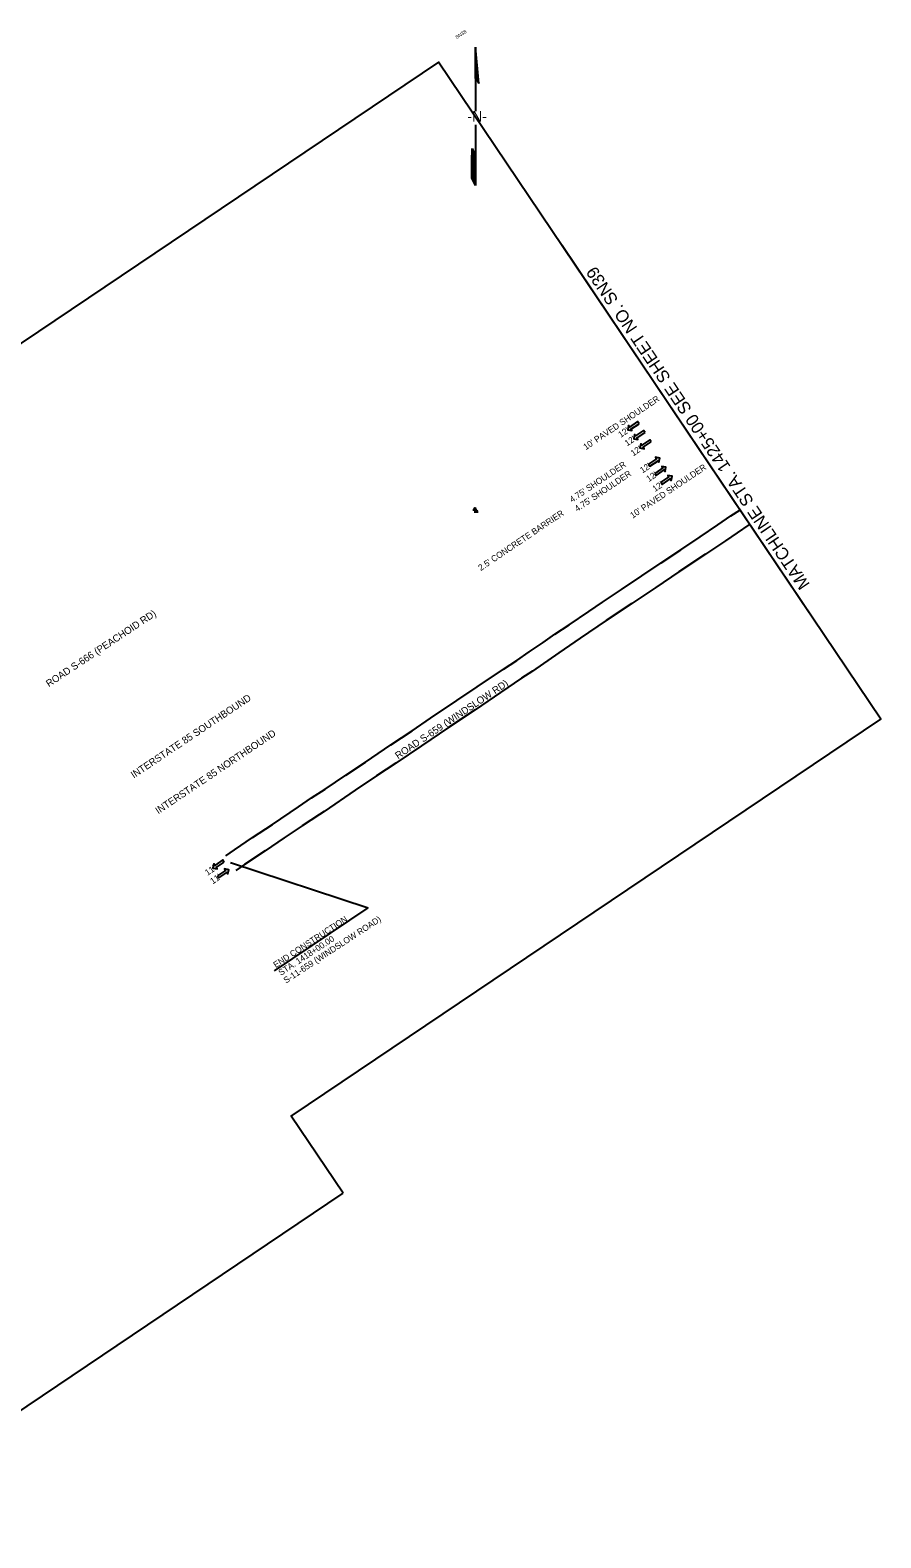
# Model space of a CAD drawing. Extents: x 1789464 to 1791208, y 1183240 to 1184943.
# Drawn here: x 1790247 to 1791208, y 1183240 to 1184943 of the extents above; entities that cross this region are included whole.
import ezdxf

# ---------------------------------------------------------------- set-up
doc = ezdxf.new("R2010")
doc.units = 0
for name, color, linetype in [('RD_EX_Road', 7, 'Continuous'), ('RD_PD_Final_LnLine', 7, 'Continuous'), ('RD_PD_Final_TX', 7, 'Continuous'), ('RD_SHT_MatchLine', 7, 'Continuous'), ('RD_SHT_ShtClip', 7, 'Continuous'), ('RD_SHT_TX', 7, 'Continuous'), ('RD_Sketch1', 7, 'Continuous'), ('RD_TX_RoadID', 7, 'Continuous'), ('SN_P_Signs', 7, 'Continuous')]:
    doc.layers.add(name, color=color, linetype=linetype)

# ---------------------------------------------------------------- blocks, each defined once
blk = doc.blocks.new('NA5')
at = {"layer": 'RD_Sketch1'}
for p, q in [((47.5, 65.9), (26.8, 37.4)), ((26.8, 30.6), (47.5, 65.9)), ((27.2, 37.5), (14.5, 19.8)), ((28.1, 38.3), (26.8, 30.6)), ((14.5, 19.8), (5.5, 7.2)), ((-3.5, -5.3), (-18.5, -26.3)), ((-18.5, -26.3), (-43.3, -60.9)), ((-30.6, -36.2), (-22.3, -24.7)), ((-22.3, -24.7), (-24, -34)), ((-41.6, -51.6), (-30.6, -36.2)), ((-43.3, -60.9), (-41.6, -51.6))]:
    blk.add_line(p, q, dxfattribs=at)
for points in [[(27.1, 37.6), (39.2, 54.5)], [(27.4, 37.8), (47.4, 65.8)], [(27.6, 37.9), (46.9, 64.9)], [(27.6, 35.5), (39, 51.5)], [(27.7, 36.2), (40.6, 54.2)], [(27.7, 36), (40.1, 53.3)], [(27.7, 35.8), (39.6, 52.4)], [(27.8, 38.1), (46.4, 64)], [(27.8, 36.8), (42.2, 56.8)], [(27.8, 36.6), (41.7, 56)], [(27.8, 36.4), (41.1, 55.1)], [(27.9, 37.4), (43.8, 59.5)], [(27.9, 37.2), (43.2, 58.6)], [(27.9, 37), (42.7, 57.7)], [(28, 38.1), (45.3, 62.2)], [(28, 37.9), (44.8, 61.3)], [(28, 37.7), (44.3, 60.4)], [(28.1, 38.3), (45.8, 63.1)], [(26.9, 37.5), (29.9, 41.7)], [(27, 32), (30.1, 36.3)], [(27, 31.8), (29.6, 35.4)], [(27, 31.5), (29.1, 34.5)], [(27.1, 32.6), (31.7, 39)], [(27.1, 32.4), (31.2, 38.1)], [(27.1, 32.2), (30.6, 37.2)], [(27.2, 33.2), (33.3, 41.6)], [(27.2, 33), (32.7, 40.7)], [(27.2, 32.8), (32.2, 39.9)], [(27.3, 33.9), (34.8, 44.3)], [(27.3, 33.7), (34.3, 43.4)], [(27.3, 33.4), (33.8, 42.5)], [(27.4, 34.5), (36.4, 47)], [(27.4, 34.3), (35.9, 46.1)], [(27.4, 34.1), (35.4, 45.2)], [(27.5, 34.9), (37.5, 48.8)], [(27.5, 34.7), (36.9, 47.9)], [(27.6, 35.3), (38.5, 50.6)], [(27.6, 35.1), (38, 49.7)], [(26.8, 30.7), (27, 30.9)], [(26.9, 31.3), (28.5, 33.6)], [(26.9, 31.1), (28, 32.7)], [(26.9, 30.9), (27.5, 31.8)], [(-43.3, -60.8), (-24, -33.9)], [(-43.2, -60.1), (-23.9, -33.2)], [(-43.2, -60.3), (-23.9, -33.4)], [(-43.2, -60.5), (-24, -33.6)], [(-43.1, -59.7), (-23.8, -32.8)], [(-43.1, -59.9), (-23.9, -33)], [(-43, -59), (-23.7, -32.1)], [(-43, -59.2), (-23.7, -32.3)], [(-43, -59.4), (-23.8, -32.5)], [(-42.9, -58.6), (-23.6, -31.7)], [(-42.9, -58.8), (-23.7, -31.9)], [(-42.8, -58.1), (-23.5, -31.2)], [(-42.8, -58.3), (-23.6, -31.4)], [(-42.7, -57.5), (-23.4, -30.6)], [(-42.7, -57.7), (-23.5, -30.8)], [(-42.7, -57.9), (-23.5, -31)], [(-42.6, -57), (-23.3, -30.1)], [(-42.6, -57.2), (-23.4, -30.4)], [(-42.5, -56.4), (-23.2, -29.5)], [(-42.5, -56.6), (-23.2, -29.7)], [(-42.5, -56.8), (-23.3, -29.9)], [(-42.4, -55.9), (-23.1, -29)], [(-42.4, -56.1), (-23.2, -29.3)], [(-42.3, -55.3), (-23, -28.4)], [(-42.3, -55.5), (-23, -28.6)], [(-42.3, -55.7), (-23.1, -28.8)], [(-42.2, -54.8), (-22.9, -27.9)], [(-42.2, -55), (-23, -28.2)], [(-42.1, -54.4), (-22.8, -27.5)], [(-42.1, -54.6), (-22.9, -27.7)], [(-42, -53.7), (-22.7, -26.8)], [(-42, -53.9), (-22.7, -27.1)], [(-42, -54.2), (-22.8, -27.3)], [(-41.9, -53.3), (-22.6, -26.4)], [(-41.9, -53.5), (-22.7, -26.6)], [(-41.8, -52.6), (-22.5, -25.7)], [(-41.8, -52.8), (-22.5, -26)], [(-41.8, -53.1), (-22.6, -26.2)], [(-41.7, -52.2), (-22.4, -25.3)], [(-41.7, -52.4), (-22.5, -25.5)], [(-41.6, -51.7), (-22.3, -24.9)], [(-41.6, -52), (-22.4, -25.1)]]:
    blk.add_lwpolyline(points, dxfattribs=at)
blk.add_text('-N-', height=11.81, rotation=324.3865, dxfattribs=at).set_placement((-8.8, 3))
blk = doc.blocks.new('SARRW2')
at = {"layer": 'RD_PD_Final_LnLine'}
blk.add_lwpolyline([(-12, 1.2), (-12, -1.2), (-2.8, -1.2), (-2.8, -2.8), (0, 0), (-2.8, 2.8), (-2.8, 1.2)], close=True, dxfattribs=at)

msp = doc.modelspace()

# ---------------------------------------------------------------- linework, layer by layer
at = {"layer": 'RD_EX_Road'}
for points in [[(1790468.4, 1184010.8), (1790478.3, 1184017.5), (1790498.6, 1184031.4), (1790521.1, 1184046.2), (1790550.5, 1184066.1), (1790565.3, 1184076), (1790580.8, 1184086), (1790603.9, 1184101.6), (1790626.2, 1184116.6), (1790654.7, 1184135.9), (1790678.9, 1184152), (1790699.8, 1184166.2), (1790729.5, 1184186.3), (1790752.4, 1184201.5), (1790782.3, 1184221.4), (1790797, 1184231.5), (1790811.2, 1184241.1), (1790826.9, 1184251.6), (1790840.3, 1184260.9), (1790856.3, 1184271.5), (1790878.6, 1184286.5), (1790894, 1184297.1), (1790915.3, 1184311.5), (1790938.3, 1184326.9), (1790960.4, 1184341.7), (1790982.5, 1184356.4), (1791004.3, 1184371.2), (1791024.1, 1184384.5), (1791039.1, 1184394.7), (1791049, 1184401.3), (1791049.3, 1184401.5)], [(1791060.3, 1184385.1), (1791059.4, 1184384.4), (1791032.8, 1184366.5), (1791010.3, 1184351.4), (1790980.3, 1184331.3), (1790954.1, 1184313.8), (1790927.1, 1184295.8), (1790898.3, 1184276.4), (1790868.8, 1184256.4), (1790844.6, 1184239.9), (1790814.7, 1184219.4), (1790802.5, 1184211.2), (1790778.8, 1184195.1), (1790750.1, 1184175.7), (1790720.1, 1184155.6), (1790689.3, 1184135), (1790660.6, 1184115.5), (1790638.8, 1184100.9), (1790614.5, 1184084.8), (1790579.4, 1184060.9), (1790574.1, 1184057.4), (1790554.5, 1184044.5), (1790534.4, 1184030.9), (1790513, 1184016.4), (1790489.6, 1184000.7), (1790479.7, 1183994.1)]]:
    msp.add_lwpolyline(points, dxfattribs=at)
at = {"layer": 'RD_PD_Final_TX'}
for p in [(1790473.5, 1184003.2), (1790523.5, 1183880.7)]:
    msp.add_line(p, (1790629.3, 1183951.9), dxfattribs=at)
at = {"layer": 'RD_SHT_MatchLine'}
msp.add_lwpolyline([(1791127.5, 1184285.3), (1790987.9, 1184492.7), (1790848.3, 1184700)], dxfattribs=at)
at = {"layer": 'RD_SHT_ShtClip'}
msp.add_lwpolyline([(1790601, 1183629.5), (1790542.4, 1183716.6), (1791208.5, 1184165), (1790708.7, 1184907.4), (1790708.7, 1184907.4), (1789464.3, 1184069.8), (1790022.8, 1183240.2)], close=True, dxfattribs=at)
at = {"layer": 'SN_P_Signs'}
for p, q in [((1790747.6, 1184401.6), (1790752.1, 1184401.6)), ((1790749, 1184399.1), (1790753.5, 1184399.1))]:
    msp.add_line(p, q, dxfattribs=at)
for centre in [(1790749.9, 1184402.6), (1790751.3, 1184400.1)]:
    msp.add_circle(centre, 1, dxfattribs=at)

# ---------------------------------------------------------------- block references
at = {"layer": 'RD_PD_Final_LnLine', "xscale": 1.1999999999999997}
for p, yscale, rotation in [((1790922.5, 1184492), 1.2000000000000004, -146.05256015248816), ((1790929.3, 1184481.9), 1.2000000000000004, -146.05256015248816), ((1790936.3, 1184471.5), 1.2000000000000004, -146.05256015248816), ((1790958.7, 1184460), 1.2, 33.94743984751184), ((1790965.7, 1184449.6), 1.2, 33.94743984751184), ((1790972.5, 1184439.5), 1.2, 33.94743984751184), ((1790453.9, 1183996.8), 1.2000000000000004, -146.05256015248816), ((1790471.7, 1183994.9), 1.2, 33.94743984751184)]:
    msp.add_blockref('SARRW2', p, dxfattribs=dict(at, yscale=yscale, rotation=rotation))
at = {"layer": 'RD_SHT_MatchLine', "rotation": 35.61349782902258}
msp.add_blockref('NA5', (1790750.3, 1184842.8), dxfattribs=at)

# ---------------------------------------------------------------- texts
at = {"layer": 'RD_PD_Final_TX'}
for s, rotation, p in [("10' PAVED SHOULDER", 33.9474, (1790875.2, 1184468.8)), ("12'", 33.9474, (1790914.6, 1184482.7)), ("12'", 33.9474, (1790921.8, 1184473.1)), ("12'", 33.9474, (1790928.7, 1184461.8)), ("4.75' SHOULDER", 33.9474, (1790859.5, 1184409.4)), ("10' PAVED SHOULDER", 33.9474, (1790928.1, 1184391.5)), ("12'", 33.9474, (1790939.2, 1184442.5)), ("4.75' SHOULDER", 33.9474, (1790865.4, 1184399.1)), ("12'", 33.9474, (1790946.3, 1184432.8)), ("12'", 33.9474, (1790953.3, 1184421.5)), ("2.5' CONCRETE BARRIER", 33.9474, (1790756.5, 1184332.3)), ("11'", 33.9474, (1790447.7, 1183988)), ("11'", 33.9474, (1790453.6, 1183978.3)), ('END CONSTRUCTION', 33.3208, (1790524.9, 1183883.7)), ('S-11-659 (WINDSLOW ROAD)', 33.3208, (1790536.4, 1183866.2)), ('STA. 1418+00.00', 33.3208, (1790530.7, 1183875))]:
    msp.add_text(s, height=7, rotation=rotation, dxfattribs=at).set_placement(p)
at = {"layer": 'RD_SHT_MatchLine'}
msp.add_text('MATCHLINE STA. 1425+00 SEE SHEET NO. SN39', height=14, rotation=123.9476, dxfattribs=at).set_placement((1791128.8, 1184317.4))
at = {"layer": 'RD_SHT_TX'}
msp.add_text('SN38', height=4, rotation=33.9476, dxfattribs=at).set_placement((1790729.4, 1184933.1))
at = {"layer": 'RD_TX_RoadID'}
for s, rotation, p in [('ROAD S-666 (PEACHOID RD)', 33.7094, (1790268.5, 1184201)), ('ROAD S-659 (WINDSLOW RD)', 33.8066, (1790663, 1184119.6)), ('INTERSTATE 85 SOUTHBOUND', 33.7917, (1790364.4, 1184097.9)), ('INTERSTATE 85 NORTHBOUND', 33.8703, (1790392.1, 1184057.5))]:
    msp.add_text(s, height=8, rotation=rotation, dxfattribs=at).set_placement(p)

doc.saveas('drawing.dxf')
